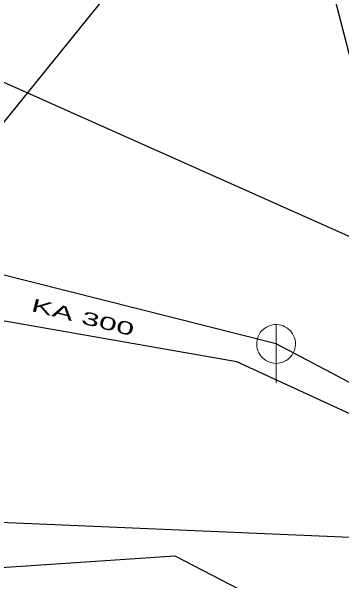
# Model space of a CAD drawing. Extents: x -687593 to -687108, y -975254 to -974717.
# Drawn here: x -687472.85 to -687455.83, y -974906.1 to -974876.79 of the extents above; entities that cross this region are included whole.
import ezdxf
from ezdxf.enums import TextEntityAlignment as Align

# ---------------------------------------------------------------- set-up
doc = ezdxf.new("R2010")
doc.units = 0
doc.header["$LTSCALE"] = 0.27
for name, color, linetype, lineweight in [('1', 7, 'Continuous', 25), ('14', 7, 'Continuous', 13), ('17', 7, 'Continuous', 25), ('22', 7, 'Continuous', 13)]:
    doc.layers.add(name, color=color, linetype=linetype, lineweight=lineweight)

msp = doc.modelspace()

# ---------------------------------------------------------------- linework, layer by layer
at = {"layer": '1'}
msp.add_lwpolyline([(-687190.553, -975166.941), (-687164.86, -975177.861), (-687155.924, -975158.837), (-687125.348, -975155.541), (-687124.826, -975139.621), (-687173.065, -975131.89), (-687231.828, -975028.025), (-687222.959, -975015.464), (-687237.898, -975004.026), (-687247.4, -975009.654), (-687276.892, -974983.781), (-687453.606, -974886.044), (-687460.232, -974860.45), (-687474.874, -974858.564), (-687482.889, -974882.272), (-687502.421, -974882.802), (-687499.452, -974907.164), (-687464.42, -974904.824), (-687331.319, -974973.728), (-687252.566, -975037.916), (-687192.379, -975151.48)], close=True, dxfattribs=at)
at = {"layer": '14', "lineweight": 25}
for p, q in [((-687462.829, -974869.623), (-687478.559, -974889.03)), ((-687459.21, -974893.91), (-687478.559, -974889.03)), ((-687436.91, -974905.59), (-687459.21, -974893.91))]:
    msp.add_line(p, q, dxfattribs=at)
at = {"layer": '17'}
for points in [[(-687435.81, -974897.134), (-687436.384, -974896.879), (-687476.987, -974878.778), (-687472.749, -974868.359), (-687469.87, -974842.274), (-687463.434, -974780.208), (-687461.035, -974770.463), (-687454.798, -974755.022), (-687445.204, -974742.578), (-687440.405, -974737.48), (-687422.229, -974716.702)], [(-687440.137, -974904.525), (-687461.23, -974894.833), (-687480.87, -974891.39), (-687481.12, -974891.28)], [(-687397.965, -974929.018), (-687440.137, -974904.525), (-687515.147, -974901.318)]]:
    msp.add_lwpolyline(points, dxfattribs=at)
at = {"layer": '22'}
msp.add_line((-687459.21, -974895.91), (-687459.209, -974892.91), dxfattribs=at)
msp.add_lwpolyline([(-687458.21, -974893.91), (-687458.215, -974893.801), (-687458.233, -974893.693), (-687458.263, -974893.587), (-687458.303, -974893.486), (-687458.355, -974893.389), (-687458.417, -974893.299), (-687458.489, -974893.216), (-687458.569, -974893.142), (-687458.657, -974893.076), (-687458.751, -974893.021), (-687458.851, -974892.976), (-687458.956, -974892.943), (-687459.063, -974892.921), (-687459.172, -974892.911), (-687459.282, -974892.913), (-687459.39, -974892.927), (-687459.497, -974892.952), (-687459.6, -974892.989), (-687459.698, -974893.038), (-687459.79, -974893.096), (-687459.876, -974893.165), (-687459.953, -974893.242), (-687460.022, -974893.328), (-687460.081, -974893.42), (-687460.129, -974893.518), (-687460.166, -974893.621), (-687460.192, -974893.728), (-687460.206, -974893.836), (-687460.209, -974893.946), (-687460.199, -974894.055), (-687460.178, -974894.162), (-687460.144, -974894.266), (-687460.1, -974894.366), (-687460.045, -974894.461), (-687459.979, -974894.549), (-687459.905, -974894.629), (-687459.822, -974894.701), (-687459.732, -974894.763), (-687459.636, -974894.815), (-687459.534, -974894.856), (-687459.429, -974894.886), (-687459.321, -974894.904), (-687459.211, -974894.91), (-687459.102, -974894.904), (-687458.994, -974894.886), (-687458.889, -974894.857), (-687458.787, -974894.816), (-687458.69, -974894.764), (-687458.6, -974894.702), (-687458.517, -974894.631), (-687458.442, -974894.551), (-687458.377, -974894.463), (-687458.321, -974894.369), (-687458.277, -974894.269), (-687458.243, -974894.165), (-687458.221, -974894.057), (-687458.211, -974893.948)], close=True, dxfattribs=at)

# ---------------------------------------------------------------- texts
at = {"layer": '1', "width": 1.85}
msp.add_text('KA 300', height=0.6667, rotation=346, dxfattribs=at).set_placement((-687469.2446, -974892.8576), align=Align.CENTER)
msp.add_text('KA 300', height=0.6667, rotation=346, dxfattribs=at).set_placement((-687469.2446, -974892.8576), align=Align.CENTER)
msp.add_text('KA 300', height=0.6667, rotation=346, dxfattribs=at).set_placement((-687469.2446, -974892.8576), align=Align.CENTER)
msp.add_text('KA 300', height=0.6667, rotation=346, dxfattribs=at).set_placement((-687469.2446, -974892.8576), align=Align.CENTER)
msp.add_text('KA 300', height=0.6667, rotation=346, dxfattribs=at).set_placement((-687469.2446, -974892.8576), align=Align.CENTER)

doc.saveas('drawing.dxf')
